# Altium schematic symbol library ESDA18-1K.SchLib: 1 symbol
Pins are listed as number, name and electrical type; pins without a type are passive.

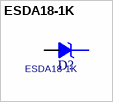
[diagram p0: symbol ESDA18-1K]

## ESDA18-1K
designator D?
footprint ST_SOD523
pins: 1 K, 2 A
